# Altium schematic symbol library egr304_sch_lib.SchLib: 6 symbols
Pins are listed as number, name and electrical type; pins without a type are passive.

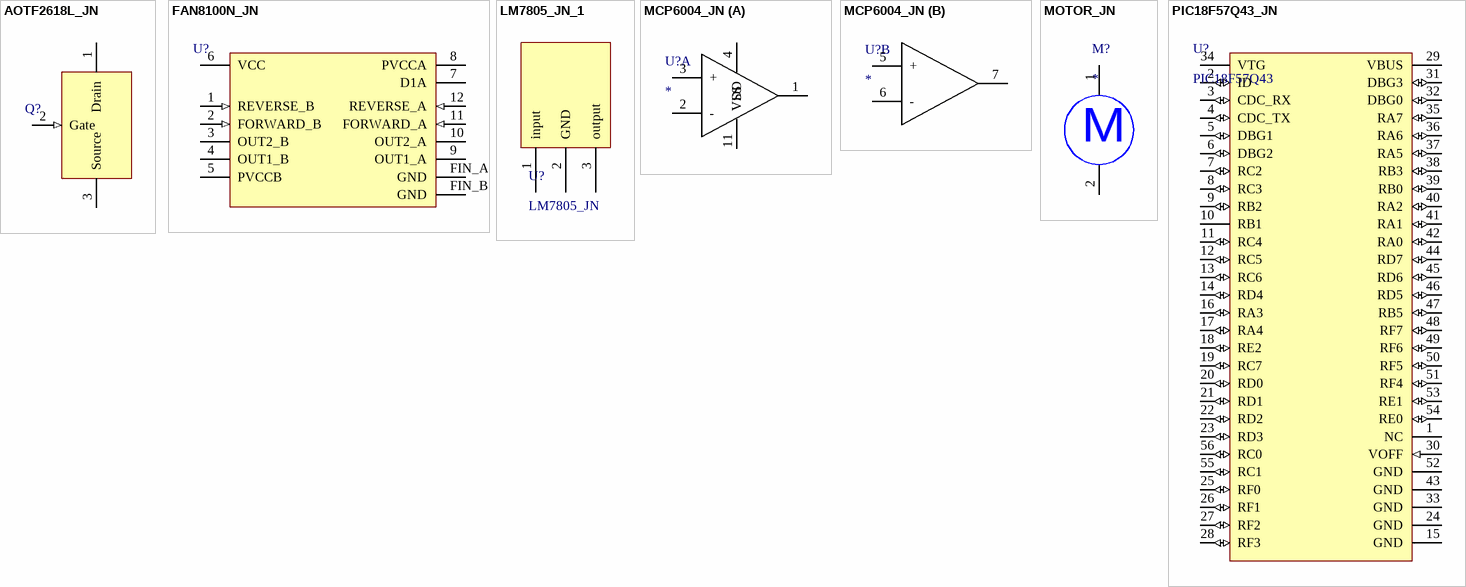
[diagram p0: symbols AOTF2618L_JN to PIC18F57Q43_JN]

## AOTF2618L_JN
designator Q?  (value not drawn)
MOSFET
footprint AOT_JN
pins: 1 Drain (power), 2 Gate (in), 3 Source (power)

## FAN8100N_JN
designator U?  (value not drawn)
H-Bridge Motor Driver
footprint FAN8100N_JN
pins: 1 REVERSE_B (in), 2 FORWARD_B (in), 3 OUT2_B, 4 OUT1_B, 5 PVCCB (power), 6 VCC (power), 7 D1A (power), 8 PVCCA (power), 9 OUT1_A, 10 OUT2_A, 11 FORWARD_A (in), 12 REVERSE_A (in), FIN_A GND (power), FIN_B GND (power)

## LM7805_JN_1
designator U?, comment LM7805_JN
footprint LM7805_JN
pins: 1 input, 2 GND, 3 output (power)

## MCP6004_JN
designator U?
footprint MCP6004_JN
part A pins: 1 (power), 2 - (power), 3 + (power), 4 VDD (power), 11 VSS (power)
part B pins: 5 + (power), 6 - (power), 7 (power)

## MOTOR_JN
designator M?
DC Motor
footprint MOTOR_JN
pins: 1 V1, 2 V2

## PIC18F57Q43_JN
designator U?, comment PIC18F57Q43
footprint PIC1857Q43_JN
pins: 1 NC (power), 2 ID (io), 3 CDC_RX (io), 4 CDC_TX (io), 5 DBG1 (io), 6 DBG2 (io), 7 RC2 (io), 8 RC3 (io), 9 RB2 (io), 10 RB1, 11 RC4 (io), 12 RC5 (io), 13 RC6 (io), 14 RD4 (io), 15 GND (power), 16 RA3 (io), 17 RA4 (io), 18 RE2 (io), 19 RC7 (io), 20 RD0 (io), 21 RD1 (io), 22 RD2 (io), 23 RD3 (io), 24 GND (power), 25 RF0 (io), 26 RF1 (io), 27 RF2 (io), 28 RF3 (io), 29 VBUS (power), 30 VOFF (in), 31 DBG3 (io), 32 DBG0 (io), 33 GND (power), 34 VTG (power), 35 RA7 (io), 36 RA6 (io), 37 RA5 (io), 38 RB3 (io), 39 RB0 (io), 40 RA2 (io), 41 RA1 (io), 42 RA0 (io), 43 GND (power), 44 RD7 (io), 45 RD6 (io), 46 RD5 (io), 47 RB5 (io), 48 RF7 (io), 49 RF6 (io), 50 RF5 (io), 51 RF4 (io), 52 GND (power), 53 RE1 (io), 54 RE0 (io), 55 RC1 (io), 56 RC0 (io)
